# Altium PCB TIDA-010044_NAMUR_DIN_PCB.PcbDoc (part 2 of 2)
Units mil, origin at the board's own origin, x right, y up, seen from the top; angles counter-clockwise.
Board outline 1290 x 2860 mil, 2 copper layers (Top Layer, Bottom Layer), stack 62 mil thick; 85 components, 49 nets, 226 pads, 57 vias.
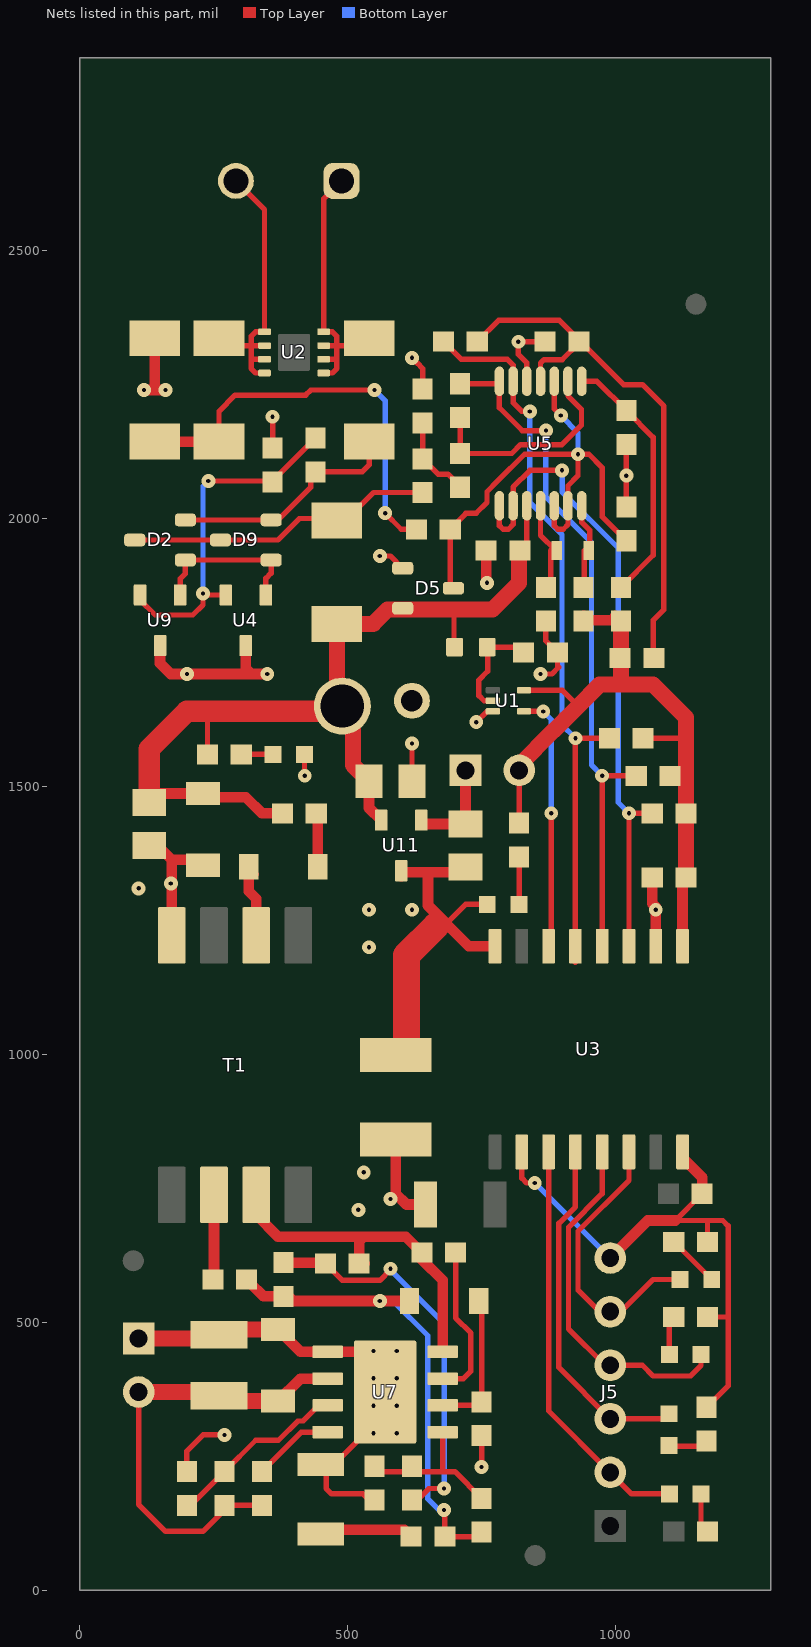
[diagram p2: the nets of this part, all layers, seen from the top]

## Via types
v1: diameter 26, hole 7.87, Top Layer to Bottom Layer, tented both sides, 44 vias
v2: diameter 19.68, hole 7.87, Top Layer to Bottom Layer, 8 vias
v3: diameter 19.68, hole 7.87, Top Layer to Bottom Layer, tented both sides, 4 vias
v4: diameter 26/26 (per signal layer), hole 7.87, Top Layer to Bottom Layer, tented both sides, 1 vias

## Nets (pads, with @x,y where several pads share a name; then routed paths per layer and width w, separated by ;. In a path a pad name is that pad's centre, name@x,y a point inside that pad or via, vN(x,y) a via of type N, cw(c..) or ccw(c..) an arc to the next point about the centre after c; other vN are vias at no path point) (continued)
GND: C5.1 C7.2 C8.2 C9.2 C10.2 C16.2 J1.1 R38.1 R39.1 U7.1 U7.9@570,370 | length 1192.6
  Top Layer w10: R39.1@200,221.5 200,260 230,290 v1(270,290) ; C10.2@450,227.09 460,217.09 460,190 470,180 528.5,180 R38.1@550,158.5 ; C10.2@476,240 480,240 570,330 U7.9@570,370 570,410 530,450 U7.9@525,445 ; v1@750,240 C9.2@750,288.5
  Top Layer w20: C7.2@370,486.93 411.93,445 U7.1@462.72,445 U7.9@525,445 ; C5.1@590,841.26 590,740 610,720 C16.2@645.04,720
  Top Layer w30: J1.1@110,470 252.91,470 C8.2@260,477.09 269.84,486.93 C7.2@370,486.93
  other v1: 750,230 520,710 580,730 530,780
  other v2: 548.35,344.41 591.65,344.41 548.35,395.59 591.65,395.59
  other v3: 548.35,293.23 591.65,293.23 548.35,446.77 591.65,446.77
In1_Failure: R10.1 U3.3 U5.1 U5.2 | length 1226.7
  Top Layer w10: U5.1@783.23,2023.86 783.23,1986.77 790,1980 800,1980 808.82,1988.82 U5.2@808.82,2023.86 808.82,2058.82 840,2090 v1(900.26,2090) ; U3.3@1025,1201.93 v1(1025,1450) R10.1@1068.5,1450
  Bottom Layer w10: v1(900.26,2090) 900.26,2049.74 1005,1945 1005,1470 v1(1025,1450)
In1_neg: J2.2 R13.2 U2.5 U2.6 U2.7 U2.8 | length 535.6
  Top Layer w10: R13.2@260,2336.46 273.66,2322.8 U2.6@344.88,2322.8 ; J2.2@291.57,2630 344.88,2576.69 U2.5@344.88,2348.39 328.39,2348.39 320,2340 320,2322.8 320,2297 320,2280 328.39,2271.61 U2.8@344.88,2271.61 ; 320.2,2297.2 U2.7@344.88,2297.2
In1_pos: J2.1 R2.2 U2.1 U2.2 U2.3 U2.4 | length 527.6
  Top Layer w10: U2.1@455.12,2271.61 471.61,2271.61 480,2280 480,2297 ; U2.2@455.12,2297.2 479.8,2297.2 480,2297 ; U2.3@455.12,2322.8 480,2322.8 ; J2.1@488.43,2630 455.12,2596.69 U2.4@455.12,2348.39 471.61,2348.39 480,2340 480,2322.8 ; R2.2@540,2336.46 526.34,2322.8 480,2322.8 ; 480,2297 480,2322.8
In1_Powfail: U1.4 U3.6 | length 487.4
  Top Layer w10: U1.4@829.13,1640.32 869.68,1640.32 v1@870,1640 ; U3.6@875,1201.93 880,1206.93 v1(880,1450)
  Bottom Layer w10: v1(865,1640) 880,1625 v1(880,1450)
In1_ShortErr: R3.1 R44.2 U3.4 U5.14 | length 1295.2
  Top Layer w10: R44.2@710,2251.5 778.58,2251.5 U5.14@783.23,2256.14 783.23,2206.77 825.87,2164.13 v1(870,2164.13) ; U3.4@975,1201.93 975,1515 980,1520 R3.1@1038.5,1520
  Bottom Layer w10: v1(870,2164.13) 870,2040 955,1955 955,1540 v1(975,1520)
In1_Status: R14.1 R26.2 U3.5 U5.13 | length 1382.9
  Top Layer w10: R26.2@678.82,2330.32 712.13,2297 798,2297 808.82,2286.18 U5.13@808.82,2256.14 808.82,2216.18 825,2200 v1(840,2200) ; U3.5@925,1171.93 U3.5@925,1201.93 925,1450 v1(925,1590) R14.1@988.5,1590
  Bottom Layer w10: v1(840,2200) 840,2030 900,1970 900,1615 v1(925,1590)
ISO_GND: C1.2 C4.1 C5.2 C11.2 C13.2 C14.2 C15.2 C18.2 D4.2 D5.1 D15.2 J4.1 R7.1 R8.1 R12.1 R17.2 R22.1 R23.1 R50.1 T1.4 U1.3 U3.2 U3.8 U4.3 U5.12 U9.3 U11.3 | length 2243.7
  Top Layer w10: R8.1@360,2131.5 v1(360,2190) ; D4.2@419.53,1560 419.53,1520.47 v1(420,1520) ; v1(560,1930) 580,1930 D5.1@602.76,1907.24 ; C1.2@620,1510 v1(620,1580) ; 630,2290 640,2280 R22.1@640,2241.5 ; 687,1247 720,1280 D15.2@760.47,1280 ; v1(740,1620) 760.32,1640.32 U1.3@770.87,1640.32 ; U5.12@834.41,2256.14 834.41,2290.59 818.5,2306.5 v1(818.5,2330) R50.1@868.5,2330 ; v1(860,1710) 881.27,1710 894,1722.73 891.5,1725.24 R7.1@891.5,1750 870,1771.5 R23.1@870,1808.5 ; C11.2@1020,2021.5 R17.2@1020,2125.55
  Top Layer w20: v1(120,2240) v4(160,2240) ; C14.2@140,1380 155,1380 171.89,1363.11 ; R12.1@140,2336.46 140,2242 142,2240 ; U9.3@150,1762.76 150,1730 170,1710 v1(200,1710) 320,1710 ; T1.4@171.89,1222.13 171.89,1318.97 171.89,1363.11 ; C13.2@230,1353.07 219.96,1363.11 171.89,1363.11 ; U4.3@310,1762.76 310,1720 320,1710 ; v1(350,1710) 320,1710 ; U11.3@600,1332.76 607.24,1340 650,1340 ; C15.2@720,1340 680,1340 650,1340 ; C4.1@758.5,1940 758.5,1881.5 v1(760,1880) ; U3.8@775,1201.93 726.07,1201.93 650,1278 650,1340 ; C18.2@1068.5,1330 1068.5,1281.5 1075,1275 U3.2@1075,1201.93
  Top Layer w50: C5.2@610,998.74 610,1185 665,1240
  other v1: 540,1200 540,1270 620,1270 1075,1270 110,1310 170,1318.97 1020,2080 620,2300
NetC2_1: C2.1 D7.2 R32.2 R34.2 R36.2 | length 919.6
  Top Layer w10: v1@680,140 681.5,138.5 R34.2@681.5,100 ; R34.2@681.5,90 R34.2@681.5,100 ; R36.2@750,108.5 741.5,100 R34.2@681.5,100
  Top Layer w20: D7.2@615.53,540 v1(560,540) 398.5,540 390,548.5 C2.1@380,548.5 342.99,548.5 R32.2@317.56,573.94 ; R32.2@317.56,573.94 R32.2@311.5,580 311.5,573.94 R32.2@317.56,573.94
  Bottom Layer w10: v1(560,540) 584.74,540 649.74,475 649.74,170.26 v1@680,140
  other v1: 680,150
NetC2_2: C2.2 C3.1 R33.2 | length 737.4
  Top Layer w10: R33.2@458.5,610 490.08,578.43 560,578.43 580,598.43 v1(580,600) ; C3.1@620,158.5 651.5,190 v1(680,190)
  Top Layer w20: C2.2@390,611.5 R33.2@458.5,611.5
  Bottom Layer w10: v1(580,600) 580,597.5 680,497.5 v1(680,190)
NetC3_2: C3.2 R36.1 R38.2 U7.5 | length 302.2
  Top Layer w10: R38.2@550,221.5 675,221.5 ; U7.5@677.28,295 677.28,223.78 675,221.5 ; R36.1@745,166.5 R36.1@750,161.5 ; R36.1@750,171.5 700,221.5 675,221.5
NetC6_1: C6.1 R33.1 T1.7 U7.8 | length 632.3
  Top Layer w20: T1.7@329.37,737.87 329.37,700.63 370,660 530,660 ; R33.1@521.5,610 521.5,651.5 530,660 ; R33.1@530,611.5 R33.1@531.5,610 ; U7.8@677.28,445 677.28,578.72 638.5,617.5 C6.1@638.5,630 608.5,660 530,660
NetC6_2: C6.2 U7.7 | length 291.3
  Top Layer w10: U7.7@677.28,395 716,395 730,409 730,480 701.5,508.5 C6.2@701.5,630
NetC7_1: C7.1 C8.1 J1.2 R35.2 R37.2 U7.2 | length 862.9
  Top Layer w10: J1.2@110,370 110,160 160,110 230,110 270,150 R37.2@270,158.5 R35.2@340,158.5
  Top Layer w20: C7.1@370,353.07 411.93,395 U7.2@462.72,395
  Top Layer w30: J1.2@110,370 252.91,370 C8.1@260,362.91 269.84,353.07 C7.1@370,353.07
NetC9_1: C9.1 D7.1 U7.6 | length 270.3
  Top Layer w10: U7.6@677.28,345 733.5,345 C9.1@750,361.5 ; D7.1@744.47,540 750,534.47 C9.1@750,361.5 ; C9.1@750,351.5 C9.1@750,361.5
NetC10_1: C10.1 R34.1 | length 173.9
  Top Layer w20: C10.1@450,112.91 605.59,112.91 R34.1@618.5,100
NetC15_1: C15.1 J3.1 U11.1 | length 184.1
  Top Layer w20: U11.1@640,1430 710,1430 720,1420 J3.1@720,1520
NetD1_1: D1.1 J5.2 U3.11 | length 772.7
  Top Layer w10: U3.11@875,818.07 875,335 J5.2@990,220 1030,180 D1.1@1100.47,180
NetD1_2: D1.2 R9.2 | length 75
  Top Layer w10: D1.2@1159.53,180 1159.53,121.97 R9.2@1171.5,110
NetD2_1: D2.1 D9.1 U4.1 U9.1 | length 298.9
  Top Layer w10: U9.1@187.4,1857.24 187.4,1887.4 197.24,1897.24 D2.1@197.24,1922.6 D9.1@357.24,1922.6 357.24,1898.24 347.4,1888.4 U4.1@347.4,1857.24
NetD2_2: D2.2 D9.2 R2.1 R6.2 | length 440.5
  Top Layer w10: D2.2@197.24,1997.4 D9.2@357.24,1997.4 370.4,1997.4 431,2058 431,2078.01 R6.2@440,2087.01 527.01,2087.01 540,2100 R2.1@540,2143.54
NetD4_1: D4.1 R31.1 | length 59
  Top Layer w10: R31.1@301.5,1560 D4.1@360.47,1560
NetD6_1: D6.1 R29.1 | length 100.4
  Top Layer w10: R29.1@440,1448.5 R29.1@444.47,1444.04
  Top Layer w20: D6.1@444.47,1350 R29.1@444.47,1444.04
NetD6_2: D6.2 T1.2 | length 153.2
  Top Layer w10: D6.2@315.53,1350 D6.2@329.37,1336.16
  Top Layer w20: D6.2@315.53,1350 315.53,1304.47 329.37,1290.63 T1.2@329.37,1222.13
NetD11_1: D11.1 R46.2 | length 73.3
  Top Layer w10: D11.1@1100.47,440 1100.47,501.97 R46.2@1108.5,510
NetD11_2: D11.2 J5.4 U3.13 | length 668.6
  Top Layer w10: U3.13@975,818.07 975,740.28 912.13,677.4 912.13,487.87 980,420 J5.4@990,420 1050,420 1070,400 1140,400 1159.53,419.53 D11.2@1159.53,440
NetD14_1: D14.1 R48.2 | length 73.3
  Top Layer w10: D14.1@1100,260.47 1108.03,268.5 R48.2@1170,268.5
NetD14_2: D14.2 J5.3 U3.12 | length 660.7
  Top Layer w10: U3.12@925,818.07 925,715.56 894.25,684.81 894.25,415.75 J5.3@990,320 1099.53,320 D14.2@1100,319.53
NetD15_1: D15.1 R11.1 | length 88.7
  Top Layer w10: D15.1@819.53,1270 820,1270.48 R11.1@820,1358.51
NetD16_1: D16.1 R20.2 | length 100
  Top Layer w10: R20.2@1108.5,650 1109.53,650 D16.1@1179.53,580
NetD16_2: D16.2 J5.5 U3.14 | length 529.3
  Top Layer w10: U3.14@1025,818.07 1025,765 930,670 930,560 970,520 J5.5@990,520 1010,520 1070,580 D16.2@1120.47,580
NetR1_1: R1.1 R17.1 U5.8 | length 482.9
  Top Layer w10: U5.8@936.77,2256.14 965.35,2256.14 R17.1@1020,2201.5 1070,2151.5 1070,1931.5 R1.1@1010,1871.5 ; R1.1@1000,1881.5 R1.1@1001.5,1881.5
NetR4_1: R4.1 R7.2 U1.2 | length 198.5
  Top Layer w10: U1.2@770.87,1660 754.39,1660 744.8,1669.59 744.8,1698.46 761.5,1715.16 761.5,1760 818.5,1760 R7.2@828.5,1750
NetR6_1: R6.1 R8.2 U4.2 U9.2 | length 654.5
  Top Layer w10: U9.2@112.6,1857.24 112.6,1848.4 141,1820 211,1820 230,1839 230,1854.49 232.76,1857.24 U4.2@272.6,1857.24 ; v1(240,2070) 358.5,2070 R8.2@360,2068.5 360,2070 R6.1@440,2150
  Bottom Layer w10: v1(230,1860) 230,2060 v1(240,2070)
NetR12_2: R12.2 R13.1 R15.2 | length 792.2
  Top Layer w10: R13.1@260,2143.54 260,2200 290.2,2230.2 421.5,2230.2 431.31,2240 v1(550,2240) ; v1(570,2010) 600,1980 R15.2@628.5,1980
  Top Layer w20: R12.2@140,2143.54 R13.1@260,2143.54
  Bottom Layer w10: v1(550,2240) 570,2220 v1(570,2010)
NetR16_1: R16.1 R18.2 U5.7 | length 149.1
  Top Layer w10: U5.7@936.77,2023.86 936.77,1993.23 951.5,1978.5 R18.2@951.5,1940 ; R16.1@940.32,1881.81 941.81,1883.31 R18.2@941.81,1940.32
NetR18_1: R18.1 R23.2 U5.4 | length 158.6
  Top Layer w10: U5.4@860,2023.86 860,1968.5 888.5,1940 R18.1@890,1941.5 ; 880,1941.5 878.82,1940.32 878.82,1883.31 R23.2@880.32,1881.81
NetR19_1: R19.1 R21.1 R22.2 | length 159.8
  Top Layer w10: R22.2@640,2178.5 R19.1@640,2111.5 668.5,2083 687,2083 710,2060 R21.1@710,2058.5
NetR21_2: R21.2 R44.1 U5.9 | length 407.5
  Top Layer w10: R44.1@710,2188.5 R21.2@710,2121.5 806.22,2121.5 822.6,2137.87 900,2137.87 936.34,2174.22 936.34,2203.65 911.18,2228.81 U5.9@911.18,2256.14
NetR26_1: R26.1 R50.2 R51.2 U5.11 | length 1033.1
  Top Layer w10: R26.1@741.81,2330.32 781.5,2370 895,2370 1015,2250 1050,2250 1090,2210 1090,1830 1070,1810 1070,1741.5 R51.2@1071.5,1740 ; U5.11@860,2256.14 860,2290 866.57,2296.57 900.43,2296.57 931.5,2327.64 R50.2@931.5,2330
NetR32_1: R32.1 T1.6 | length 158.8
  Top Layer w20: R32.1@248.5,580 250.63,582.13 T1.6@250.63,737.87
NetR35_1: R35.1 U7.4 | length 153.2
  Top Layer w10: R35.1@340,221.5 413.5,295 U7.4@462.72,295
NetR37_1: R37.1 R39.2 U7.3 | length 340
  Top Layer w10: R39.2@200,158.5 207.01,158.5 R37.1@270,221.5 328.5,280 371,280 407,316 417,316 446,345 U7.3@462.72,345
VBP_5V: C17.1 J5.6 R20.1 R46.1 R48.1 U3.10 U3.16 | length 1131.3
  Top Layer w10: U3.10@825,818.07 825,769 834,760 v1(849.13,760) ; 1108.5,687.01 1111.5,690 ; C17.1@1161.5,740 1111.5,690 ; R48.1@1170,341.5 1210,381.5 1210,510 ; R46.1@1171.5,510 1210,510 ; R20.1@1171.5,650 1171.5,688.5 1170,690 ; 1111.5,690 1170,690 ; 1170,690 1200,690 1210,680 1210,510
  Top Layer w20: J5.6@990,620 1060,690 1111.5,690 ; U3.16@1125,818.07 1125,807 1161.5,770.5 C17.1@1161.5,740
  Bottom Layer w10: v1(849.13,760) 850,760 J5.6@990,620
Vcomp1: C11.1 D5.3 R15.1 U5.5 U5.6 U5.10 | length 1000.4
  Top Layer w10: D5.3@697.24,1870 691.5,1875.75 R15.1@691.5,1980 720,2008.5 720,2010.06 739.94,2010.06 740,2010 760,2030 760,2050.06 779.94,2070 780,2070 830,2120 v1(930,2120) ; U5.5@885.59,2023.86 885.59,1986.77 892.36,1980 902.36,1980 911.18,1988.82 U5.6@911.18,2023.86 911.18,2061.18 930,2080 v1(930,2120) ; U5.10@889.45,2252.28 U5.10@885.59,2256.14 885.59,2204.41 v1(897.8,2192.2) ; C11.1@1020,1958.5 975.03,2003.48 975.03,2095.37 950.39,2120 v1(930,2120)
  Bottom Layer w10: v1(897.8,2192.2) 930,2160 v1(930,2120)
Viso_5V: C18.1 J3.2 R1.2 R3.2 R10.2 R11.2 R14.2 R16.2 R51.1 U1.5 U3.1 | length 1318.8
  Top Layer w10: R11.2@820,1421.5 J3.2@820,1540 ; U1.5@829.13,1679.69 900.31,1679.69 930,1650 ; R14.2@1051.5,1590 1131.5,1590
  Top Layer w20: R16.2@940.32,1818.82 R16.2@940.63,1818.5 ; R16.2@951.93,1810 R1.2@1011.3,1810 ; U3.1@1125,1201.93 1125,1323.5 C18.1@1131.5,1330
  Top Layer w30: J3.2@820,1540 884.13,1604.13 884.86,1604.13 905.87,1625.14 905.87,1625.87 930,1650 970,1690 1010,1690 ; R1.2@1010,1808.5 1010,1690 ; C18.1@1131.5,1330 1131.5,1590 1131.5,1628.5 1070,1690 1010,1690
Viso_12V: C1.1 C4.2 C13.1 C14.1 D5.2 R4.2 R5.1 R29.2 R31.2 TP1.1 U5.3 U11.2 | length 1853.1
  Top Layer w10: R31.2@238.5,1560 238.5,1638.5 240,1640 ; R4.2@698.5,1760 698.5,1828.5 700,1830 ; C4.2@820,1941.5 834.41,1955.91 U5.3@834.41,2023.86
  Top Layer w20: C14.1@130,1470 146.93,1486.93 C13.1@230,1486.93 236.93,1480 310,1480 340,1450 R29.2@378.5,1450 ; TP1.1@480,1640 TP1.1@510,1610 ; TP1.1@510,1630 TP1.1@510,1640 ; C1.1@540,1510 540,1459.84 U11.2@562.6,1437.24
  Top Layer w30: TP1.1@480,1640 R5.1@480,1803.54 547.76,1803.54 574.21,1830 700,1830 770,1830 820,1880 C4.2@820,1941.5 ; TP1.1@510,1630 510,1610 510,1540 C1.1@540,1510
  Top Layer w40: C14.1@130,1470 130,1570 200,1640 240,1640 TP1.1@480,1640
VZ1: D2.3 D9.3 R5.2 R19.2 | length 578.9
  Top Layer w10: D2.3@102.76,1960 D9.3@262.76,1960 370,1960 410,2000 480,2000 R5.2@480,1996.46 496.46,1996.46 548.5,2048.5 R19.2@640,2048.5
pads on no net: FID1.1 FID2.1 FID3.1 T1.1 T1.3 T1.5 T1.8 U1.1 U2.9 U3.7 U7.9@570,370
copper on no net:
  other v2: 400,2285.39 380.32,2310 419.68,2310 400,2334.61

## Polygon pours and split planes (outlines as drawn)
GND on Bottom Layer "BOTTOM_LAYER_GND_P004" (solid, remove dead copper, pour order 4): 120,790 60,730 60,130 130,60 760,60 780,80 780,570 730,620 700,620 700,650 670,680 670,760 640,790
BP_GND on Bottom Layer "BOTTOM_LAYER_BP_GND_P002" (solid, remove dead copper, pour order 2): 760,850 760,720 800,680 870,610 870,140 940,70 1181.02,70 1201.02,90 1200,91.02 1200,810 1160,850
ISO_GND on Bottom Layer "BOTTOM_LAYER_ISO_GND_P000" (solid, remove dead copper, pour order 0): 70,2390 1140,2390 1170,2360 1170,1210 1140,1180 120,1180 70,1230
ISO_GND on Top Layer "TOP_LAYER_ISO_GND_P012" (solid, remove dead copper, pour order 12): 88.33,1410 70,1391.67 70,1253.15 113.15,1210 180,1210 180,1390 178.54,1390 158.54,1410
ISO_GND on Top Layer "TOP_LAYER_ISO_GND_P010" (solid, remove dead copper, pour order 10): 530,1278.97 530,1180 640,1180 670,1210 670,1270 661.03,1278.97
GND on Top Layer "TOP_LAYER_GND_P006" (solid, remove dead copper, pour order 6): 510,840 510,710 540,680 640,680 640,840

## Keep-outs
Keep-Out Layer:
  text ".Layer_Name" at 577,-858.49 h60

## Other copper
Top Layer:
  text ".Layer_Name" at 577,-858.49 h60
Bottom Layer:
  text ".Layer_Name" at 577,-858.49 h60

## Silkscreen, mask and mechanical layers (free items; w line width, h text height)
Top Overlay:
  region: 990,2810 990,2600 1190,2600 1190,2810
  lines w6: 738.54,2260 738.54,2282.32 749.76,2293.54 ; 750,2370 750,2400 ; 979.98,1912.8 1057.2,1912.8 1060,1910
  text "POS(8.2V)" at 630,2750 h60 r270
  text "NAMUR" at 60,2730 h60 r270
  text "NEG" at 130,2690 h60 r270
  text "'.PRJ_Number'.PCB_Rev-" at 690,2490 h90
  text "isoGND" at 540,1720 h40
  text "12V" at 320,1620 h60
  text "5V" at 887,1607 h60
  text "5V" at 840,590 h60
  text "fail" at 1210,560 h50
  text "GND" at 10,540 h60 r270
  text "Fail" at 820,500 h60
  text "shrt" at 1210,420 h50
  text "24V Field" at 10,400 h60 r270
  text "Shrt" at 810,400 h60
  text "DIN" at 820,300 h60
  text "DIN" at 1210,290 h50
  text "Pow" at 810,200 h60
  text "Powfail" at 1260,80 h50 r90
  text "BP_GND" at 910,20 h60
  text ".Layer_Name" at 577,-858.49 h60
Bottom Overlay:
  text ".Layer_Name" at 577,-858.49 h60
Top Paste:
  text ".Layer_Name" at 577,-858.49 h60
Bottom Paste:
  text ".Layer_Name" at 577,-858.49 h60
Top Solder:
  text ".Layer_Name" at 577,-858.49 h60
  text ".Layer_Name" at 577,-858.49 h60
Bottom Solder:
  text ".Layer_Name" at 577,-858.49 h60
Drill Guide:
  text ".Layer_Name" at 577,-858.49 h60
M1 Board Outline:
  the board outline again, w10
  text ".Layer_Name" at 577,-858.49 h60
M2 Board Dimensions:
  rectangle: 125,-400 500,-275
  rectangle: 0,-275 125,-150
  lines w7: 0,-275 1000,-275 ; 125,-400 125,-150 ; 250,-400 250,-150 ; 500,-400 500,-150 ; 750,-400 750,-150 ; 0,-400 0,-150 1000,-150 1000,-400 0,-400
  text ".Layer_Name" at 577,-858.49 h60
M3 3D STEP Top:
  text ".Layer_Name" at 577,-858.49 h60
M4 3D STEP Bottom:
  text ".Layer_Name" at 577,-858.49 h60
M5 Assembly Top:
  lines w10: -292,-930.17 6308,-930.17 ; -292,-726.83 6310,-726.83 ; -292,-523.5 -292,-1133.5 3713,-1133.5 6310,-1133.5 6310,-523.5 -291.5,-523.5 -291.5,-1133.5 1284,-1133.5 ; 2173,-1133.5 2173,-523.5 ; 3440,-726.83 3440,-523.5 ; 4280,-726.83 4280,-523.5 ; 4902,-1140 4902,-937.17
  text "COMPONENTS MARKED 'DNP' SHOULD NOT BE POPULATED." at 1153.5,-318.5 h60
  text "ASSEMBLY VARIANT:" at 1153,-434 h60
  text ".VariantName" at 2189,-434 h60
  text "PCB VIEWED FROM TOP SIDE" at -228.5,-655.67 h60
  text "BOARD #:" at 2248,-655.67 h60
  text ".PRJ_Number" at 2793.5,-655.67 h60
  text "REV:" at 3638,-655.67 h60
  text ".PCB_Rev" at 3929.5,-655.67 h60
  text "SVN REV:" at 4476,-655.67 h60
  text ".VersionControl_RevNumber" at 4982,-655.67 h60
  text "TID #:" at 2248,-859 h60
  text ".TID" at 2793.5,-859 h60
  text "PLOT NAME =" at -228.5,-1064.34 h60
  text ".plot_File_Name" at 577,-1064.34 h60
  text "GENERATED    :" at 2250,-1064.34 h60
  text ".Print_Date" at 3119.5,-1064.34 h60
  text ".Print_Time" at 3848.5,-1064.34 h60
  text "TEXAS INSTRUMENTS" at 5113,-1064.34 h60
M6 Assembly Bottom:
  lines w10: -292.5,-727.33 6309.5,-727.33 ; -290.5,-930.67 6309.5,-930.67 ; 1115.5,-1140.5 1115.5,-937.67 ; 1737.5,-727.33 1737.5,-524 ; 2577.5,-727.33 2577.5,-524 ; 3844.5,-1134 3844.5,-524 ; 4733.5,-1134 6309,-1134 6309,-524 -292.5,-524 -292.5,-1134 2304.5,-1134 6309.5,-1134 6309.5,-524
  text "COMPONENTS MARKED 'DNP' SHOULD NOT BE POPULATED." at 6102,-318 h60
  text ".VariantName" at 5058,-434 h60
  text "ASSEMBLY VARIANT:" at 6097,-434 h60
  text ".VersionControl_RevNumber" at 1035.5,-656.17 h60
  text "SVN REV:" at 1541.5,-656.17 h60
  text ".PCB_Rev" at 2088,-656.17 h60
  text "REV:" at 2379.5,-656.17 h60
  text ".PRJ_Number" at 3224,-656.17 h60
  text "BOARD #:" at 3769.5,-656.17 h60
  text "PCB VIEWED FROM BOTTOM SIDE" at 6246,-656.17 h60
  text ".TID" at 3224,-859.5 h60
  text "TID #:" at 3769.5,-859.5 h60
  text "TEXAS INSTRUMENTS" at 904.5,-1064.84 h60
  text ".Print_Time" at 2169,-1064.84 h60
  text ".Print_Date" at 2898,-1064.84 h60
  text "GENERATED    :" at 3767.5,-1064.84 h60
  text ".plot_File_Name" at 5440.5,-1064.84 h60
  text "PLOT NAME =" at 6246,-1064.84 h60
M9 Title Sheet:
  drawing of 57 lines, arcs and shapes, not listed
  text "1" at 739.84,8036.5 h70
  text "2" at 3235.5,8036.5 h70
  text "3" at 5724.84,8036.5 h70
  text "4" at 8231.51,8036.5 h70
  text "5" at 10730.5,8036.5 h70
  text "6" at 13235.5,8036.5 h70
  text "A" at -416.5,6893.5 h70
  text "A" at 14383.5,6893.5 h70
  text "B" at -416.5,4513.5 h70
  text "B" at 14383.5,4513.5 h70
  text "C" at -416.5,2138.5 h70
  text "C" at 14383.5,2138.5 h70
  text "PROJECT TITLE:" at 11343.5,277.5 h45
  text ".PRJ_Title" at 11393.5,144.17 h70
  text "DESIGNED FOR:" at 11343.5,-23.5 h45
  text ".PRJ_Customer" at 11393.5,-163.5 h70
  text "D" at -416.5,-231.5 h70
  text "D" at 14383.5,-231.5 h70
  text "FILE NAME:" at 11343.5,-323.5 h45
  text ".PCB_File_Name_No_Path" at 11393.5,-443.5 h70
  text "Texas Instruments (TI) and/or its licensors do not warrant the accuracy or completeness of this specification" at 6374,-605.34 h45
  text "ENGINEER:" at 11343.5,-613.5 h45
  text "LAYOUT BY:" at 12848.5,-613.5 h45
  text "or any information contained therein. TI and/or its licensors do not warrant that this design will meet" at 6329.01,-718 h45
  text ".PRJ_Engineer" at 11393.5,-768.49 h70
  text ".PCB_Layout" at 12899,-768.49 h70
  text "the specifications, will be suitable for your application or fit for any particular purpose, or will operate in" at 6329.01,-830.67 h45
  text ".Layer_Name" at 577,-858.49 h60
  text "ALTIUM DESIGNER VERSION:" at 12848.5,-923.5 h45
  text "an implementation. TI and/or its licensors do not warrant that the design is production worthy. You should" at 6329.01,-943.33 h45
  text "completely validate and test your design implementation to confirm the system functionality for your application." at 6374,-1056 h45
  text ".print_Scale" at 11393.5,-1056.83 h70
  text ".Application_BuildNumber" at 12899,-1056.83 h70
  text "1" at 739.84,-1263.5 h70
  text "2" at 3235.5,-1263.5 h70
  text "3" at 5724.84,-1263.5 h70
  text "4" at 8231.51,-1263.5 h70
  text "5" at 10730.5,-1263.5 h70
  text "6" at 13235.5,-1263.5 h70
M10 Fab Notes:
  drawing of 189 lines, arcs and shapes, not listed
  text "DESIGN INFORMATION" at 12382.02,6356.17 h60
  text "MIN. TRACK WIDTH:" at 11737.46,6224.05 h60
  text "8" at 12833.7,6224.05 h60
  text "MIL" at 12988.46,6224.05 h60
  text "MIN. CLEARANCE:" at 11737.46,6099.92 h60
  text "0.2" at 12773.7,6099.93 h60
  text "mm" at 12988.46,6099.92 h60
  text "MIN. VIA PAD SIZE:" at 11737.46,5975.8 h60
  text "24" at 12803.71,5975.8 h60
  text "MIL" at 12988.46,5975.8 h60
  text "0.05mm (2MIL)" at 12432.46,5845.9 h60
  text "MINIMUM ANNULAR RING" at 11408.23,5837.67 h60
  text "EXTERNAL" at 13140.46,5837.67 h60
  text "PER" at 11608.23,5727.55 h60
  text "IPC-D-275 CLASS 2 LEVEL C" at 11828.23,5727.54 h60
  text "MIL, HOLES" at 13316.46,5627.07 h60
  text "+/-" at 12924,5618.48 h60
  text "+/-" at 13778,5618.48 h60
  text "REGISTRATION TOLERANCES:" at 11408.23,5617.42 h60
  text "METAL" at 12608,5617.42 h60
  text "5" at 13184.2,5617.42 h60
  text "3" at 14017.2,5617.42 h60
  text "MIL" at 14133.46,5617.42 h60
  text "HOLE SIZE TOLERANCE (UNLESS OTHERWISE SPECIFIED):" at 11408.23,5519.1 h60
  text "+/-" at 13778,5516.23 h60
  text "3" at 14017.2,5515.17 h60
  text "MIL" at 14133.46,5515.17 h60
  text "MATERIAL:" at 11333.46,5377.52 h60
  text "FR-4 High Tg" at 12319.9,5249 h60
  text "X" at 12175.46,5241.01 h60
  text "FR-408" at 11754.46,5236.49 h60
  text "OTHER" at 13242.46,5236.49 h60
  text "62 MIL (1.6mm) +/-10%" at 12074.56,5093.46 h60
  text "X" at 11954.46,5091.01 h60
  text "THICKNESS:" at 11408.23,5085.24 h60
  text "OTHER" at 13359.46,5085.24 h60
  text "TOLERANCE:" at 11408.23,4946.92 h60
  text "X" at 12256.46,4946.92 h60
  text "ANSI IPC-6012 TYPE 3 CLASS 2" at 12434.48,4946.92 h60
  text "OTHER +/-" at 12434.46,4802.73 h60
  text "BOW & TWIST:" at 11408.23,4657.54 h60
  text "X" at 12256.46,4657.54 h60
  text "ANSI IPC-6012 TYPE 3 CLASS 2" at 12434.48,4657.54 h60
  text "OTHER +/-" at 12434.46,4510.85 h60
  text "DRILLING:" at 11333.46,4380.23 h60
  text "NC_DRILL FILES" at 13094.46,4275.04 h60
  text "REFERENCE:" at 11408.23,4271.1 h60
  text "X" at 12065.46,4271.01 h60
  text "AS SHOWN" at 12243.46,4271.1 h60
  text "X" at 12966.46,4271.1 h60
  text "OTHER" at 13392.46,4128.85 h60
  text "PTH COPPER THICKNESS:" at 11407.91,4125.32 h60
  text "X" at 12547.14,4125.32 h60
  text "20-30 um" at 12675.14,4125.32 h60
  text "BOARD FINISH:" at 11333.46,3977.73 h60
  text "SILKSCREEN:" at 11488.68,3867.6 h60
  text "X" at 12446.46,3867.6 h60
  text "TOP" at 12563.46,3867.6 h60
  text "BOTTOM" at 13074.46,3867.6 h60
  text "SILKSCREEN COLOR:" at 11488.68,3712.41 h60
  text "X" at 12445.46,3712.41 h60
  text "WHITE" at 12563.46,3712.41 h60
  text "OTHER" at 13074.46,3712.41 h60
  text "X" at 12576.46,3568.96 h60
  text "GREEN" at 12694.46,3568.96 h60
  text "OTHER" at 13312.46,3568.96 h60
  text "SOLDER RESIST COLOR:" at 11488.68,3562.1 h60
  text "X" at 12576.46,3414.71 h60
  text "MATTE" at 12694.46,3414.71 h60
  text "SEMI-GLOSS" at 13312,3414.07 h60
  text "IMMERSION GOLD (ENIG)" at 12394.46,3241.94 h60
  text "ENEPIG" at 13732,3234.72 h60
  text "SURFACE FINISH:" at 11333.46,3233.72 h60
  text "X" at 12216.46,3233.72 h60
  text "IMM. TIN/SILVER OR EQUIV" at 11663,3096.4 h60
  text "OTHER" at 13094.46,3092.47 h60
  text "ARRAY/PANEL:" at 11333.46,2937.09 h60
  text "CUT AND TRIM PER M1 BOARD OUTLINE" at 12394.46,2928.87 h60
  text "N.C. ROUTE" at 12394.46,2792.9 h60
  text "X" at 13082.46,2792.9 h60
  text "V. SCORE" at 13260.46,2792.9 h60
  text "CERTIFICATION:" at 11333.46,2663.77 h60
  text "MATERIALS AND WORKMANSHIP FOR ALL PCBS" at 12058.46,2663.77 h60
  text "TO MEET OR EXCEED THE REQUIREMENTS OF:" at 12058.46,2569.71 h60
  text "X" at 11695.97,2441.08 h60
  text "ANSI IPC-A-600F CLASS ->" at 11823.96,2441.08 h60
  text "X" at 13471.97,2441.08 h60
  text "2" at 13581.96,2441.08 h60
  text "1" at 13266.96,2439.58 h60
  text "3" at 13935.96,2439.58 h60
  text "X" at 12507.97,2293.39 h60
  text "RoHS" at 12635.96,2293.39 h60
  text "OTHER" at 13280.36,2293.39 h60
  text "PER ORDER" at 13677.42,2293.39 h60
  text "ALL BOARDS MUST MEET OR EXCEED UL94-V0 REQUIREMENTS." at 11361,2139.57 h60
  text "PCB MUST BEAR THE UL94V-0 UL REGISTERED MATERIAL ID NUMBER" at 11361,2023.5 h60
  text "ADDITIONAL REQUIREMENTS:" at 11333.46,1854.08 h60
  text "MICROSECTION:" at 11408.23,1746.95 h60
  text "YES" at 12313.96,1746.95 h60
  text "REQUIRED" at 13175.46,1602.62 h60
  text "BARE BOARD ELEC. TEST:" at 11408.23,1599.76 h60
  text "NONE" at 12713.96,1599.76 h60
  text "X" at 13057.46,1599.76 h60
  text "PER ORDER" at 13767.46,1599.76 h60
  text "XX MIL VIAS REQUIRE NON-CONDUCTIVE FILL AND PLANARIZE" at 11576.38,1394.82 h59
  text "XX MIL VIAS REQUIRE CONDUCTIVE FILL AND PLANARIZE" at 11584.38,1290.84 h60
  text "OUTER XX MIL VIAS REQUIRE 50 OHM SINGLE-ENDED IMPEDANCE" at 11583.39,1127.46 h58
  text "LAYER 2 & 3 (INNER LAYERS) XX MIL WIDE, XX MIL SPACE / TRACES REQUIRE 100 OHM DIFFERENTIAL IMPEDANCE" at 11575.39,891.74 h60
  text ".Layer_Name" at 577,-858.49 h60
M11 Gerber Information:
  lines w10: -292,-930.17 6308,-930.17 ; -292,-726.83 6310,-726.83 ; -292,-523.5 -292,-1133.5 3713,-1133.5 6310,-1133.5 6310,-523.5 -291.5,-523.5 -291.5,-1133.5 1284,-1133.5 ; 2173,-1133.5 2173,-523.5 ; 3440,-726.83 3440,-523.5 ; 4280,-726.83 4280,-523.5 ; 4902,-1140 4902,-937.17
  text "ALL ARTWORK VIEWED FROM TOP SIDE" at -228.5,-655.67 h60
  text "BOARD #:" at 2248,-655.67 h60
  text ".PRJ_Number" at 2793.5,-655.67 h60
  text "REV:" at 3638,-655.67 h60
  text ".PCB_Rev" at 3929.5,-655.67 h60
  text "SVN REV:" at 4476,-655.67 h60
  text ".VersionControl_RevNumber" at 4982,-655.67 h60
  text "LAYER NAME =" at -228.5,-858.49 h60
  text "TID #:" at 2248,-859 h60
  text ".TID" at 2793.5,-859 h60
  text "PLOT NAME =" at -228.5,-1064.34 h60
  text ".plot_File_Name" at 577,-1064.34 h60
  text "GENERATED    :" at 2250,-1064.34 h60
  text ".Print_Date" at 3119.5,-1064.34 h60
  text ".Print_Time" at 3848.5,-1064.34 h60
  text "TEXAS INSTRUMENTS" at 5113,-1064.34 h60
M12 Stackup:
  drawing of 191 lines, arcs and shapes, not listed
  text "Layer" at 9797.84,7830 h60
  text "Name" at 10207.76,7830 h60
  text "Material" at 11137.5,7830 h60
  text "Thickness" at 11997.27,7830 h60
  text "Constant" at 12647.1,7830 h60
  text "Board Layer Stack" at 13216.96,7830 h60
  text "1" at 9797.84,7710 h60
  text "Top Overlay" at 10207.76,7710 h60
  text "2" at 9797.84,7590 h60
  text "Top Solder" at 10207.76,7590 h60
  text "Solder Resist" at 11137.5,7590 h60
  text "0.40mil" at 11997.27,7590 h60
  text "3.5" at 12647.1,7590 h60
  text "3" at 9797.84,7470 h60
  text "Top Layer" at 10207.76,7470 h60
  text "Copper" at 11137.5,7470 h60
  text "1.40mil" at 11997.27,7470 h60
  text "4" at 9797.84,7350 h60
  text "Dielectric1" at 10207.76,7350 h60
  text "FR-4" at 11137.5,7350 h60
  text "59.20mil" at 11997.27,7350 h60
  text "4.8" at 12647.1,7350 h60
  text "5" at 9797.84,7230 h60
  text "Bottom Layer" at 10207.76,7230 h60
  text "Copper" at 11137.5,7230 h60
  text "1.40mil" at 11997.27,7230 h60
  text "6" at 9797.84,7110 h60
  text "Bottom Solder" at 10207.76,7110 h60
  text "Solder Resist" at 11137.5,7110 h60
  text "0.40mil" at 11997.27,7110 h60
  text "3.5" at 12647.1,7110 h60
  text "7" at 9797.84,6990 h60
  text "Bottom Overlay" at 10207.76,6990 h60
  text ".Layer_Name" at 577,-858.49 h60
M13 Component Bodies Top:
  text ".Layer_Name" at 577,-858.49 h60
M14 Component Bodies Bottom:
  text ".Layer_Name" at 577,-858.49 h60
M15 Courtyards Top:
  text ".Layer_Name" at 577,-858.49 h60
M16 Courtyards Bottom:
  text ".Layer_Name" at 577,-858.49 h60
Drill Drawing:
  circle w10: c2108.72,2561.96 r27.63
  lines w10: 2081.09,2175.19 2094.9,2175.19 2108.72,2161.38 2122.53,2175.19 2136.34,2175.19 2122.53,2189 2136.34,2202.82 2122.53,2202.82 2108.72,2216.63 2094.9,2202.82 2081.09,2202.82 2094.9,2189 2081.09,2175.19 ; 2081.09,2285.7 2136.34,2285.7 2136.34,2340.95 2081.09,2340.95 2081.09,2285.7 ; 2081.09,2410.02 2108.72,2423.83 2136.34,2410.02 2122.53,2437.64 2136.34,2465.27 2108.72,2451.46 2081.09,2465.27 2094.9,2437.64 2081.09,2410.02 ; 2081.09,2713.91 2136.34,2713.91 2108.72,2658.66 2081.09,2713.91
  lines w12: 2031,2124.08 5262.49,2124.08 ; 2031,2745.68 5262.49,2745.68 ; 2368.86,1999.76 2368.86,2870 ; 2700.86,1999.76 2700.86,2870 ; 3337.43,1999.76 3337.43,2870 ; 3596.57,1999.76 3596.57,2870 ; 3971.72,1999.76 3971.72,2870 ; 4696.05,1999.76 4696.05,2870 ; 2031,1999.76 5262.49,1999.76 5262.49,2870 2031,2870 2031,1999.76
  text "Symbol" at 2105.59,2782.98 h72
  text "Quantity" at 2406.16,2782.98 h72
  text "Finished Hole Size" at 2738.16,2782.98 h72
  text "Plated" at 3374.72,2782.98 h72
  text "Hole Type" at 3633.86,2782.98 h72
  text "Drill Layer Pair" at 4009.02,2782.98 h72
  text "Hole Tolerance" at 4733.35,2782.98 h72
  text "57" at 2406.16,2658.66 h60
  text "7.87mil (0.200mm)" at 2738.16,2658.66 h60
  text "PTH" at 3374.72,2658.66 h60
  text "Round" at 3633.86,2658.66 h60
  text "Top Layer - Bottom Layer" at 4009.02,2658.66 h60
  text "10" at 2406.16,2534.34 h60
  text "33.47mil (0.850mm)" at 2738.16,2534.34 h60
  text "PTH" at 3374.72,2534.34 h60
  text "Round" at 3633.86,2534.34 h60
  text "Top Layer - Bottom Layer" at 4009.02,2534.34 h60
  text "1" at 2406.16,2410.02 h60
  text "40.16mil (1.020mm)" at 2738.16,2410.02 h60
  text "PTH" at 3374.72,2410.02 h60
  text "Round" at 3633.86,2410.02 h60
  text "Top Layer - Bottom Layer" at 4009.02,2410.02 h60
  text "2" at 2406.16,2285.7 h60
  text "47.24mil (1.200mm)" at 2738.16,2285.7 h60
  text "PTH" at 3374.72,2285.7 h60
  text "Round" at 3633.86,2285.7 h60
  text "Top Layer - Bottom Layer" at 4009.02,2285.7 h60
  text "1" at 2406.16,2161.38 h60
  text "80.71mil (2.050mm)" at 2738.16,2161.38 h60
  text "PTH" at 3374.72,2161.38 h60
  text "Round" at 3633.86,2161.38 h60
  text "Top Layer - Bottom Layer" at 4009.02,2161.38 h60
  text "71 Total" at 2406.16,2037.06 h60
  text ".Layer_Name" at 577,-858.49 h60
M17 Embedded Cavity:
  text ".Layer_Name" at 577,-858.49 h60
M18 Embedded Assembly:
  text ".Layer_Name" at 577,-858.49 h60
M19 Embedded Keepout:
  text ".Layer_Name" at 577,-858.49 h60

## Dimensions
0,-400 to 1000,-400 on M2 Board Dimensions
0,0 to 1290,0 on M2 Board Dimensions
0,0 to 0,2860 on M2 Board Dimensions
